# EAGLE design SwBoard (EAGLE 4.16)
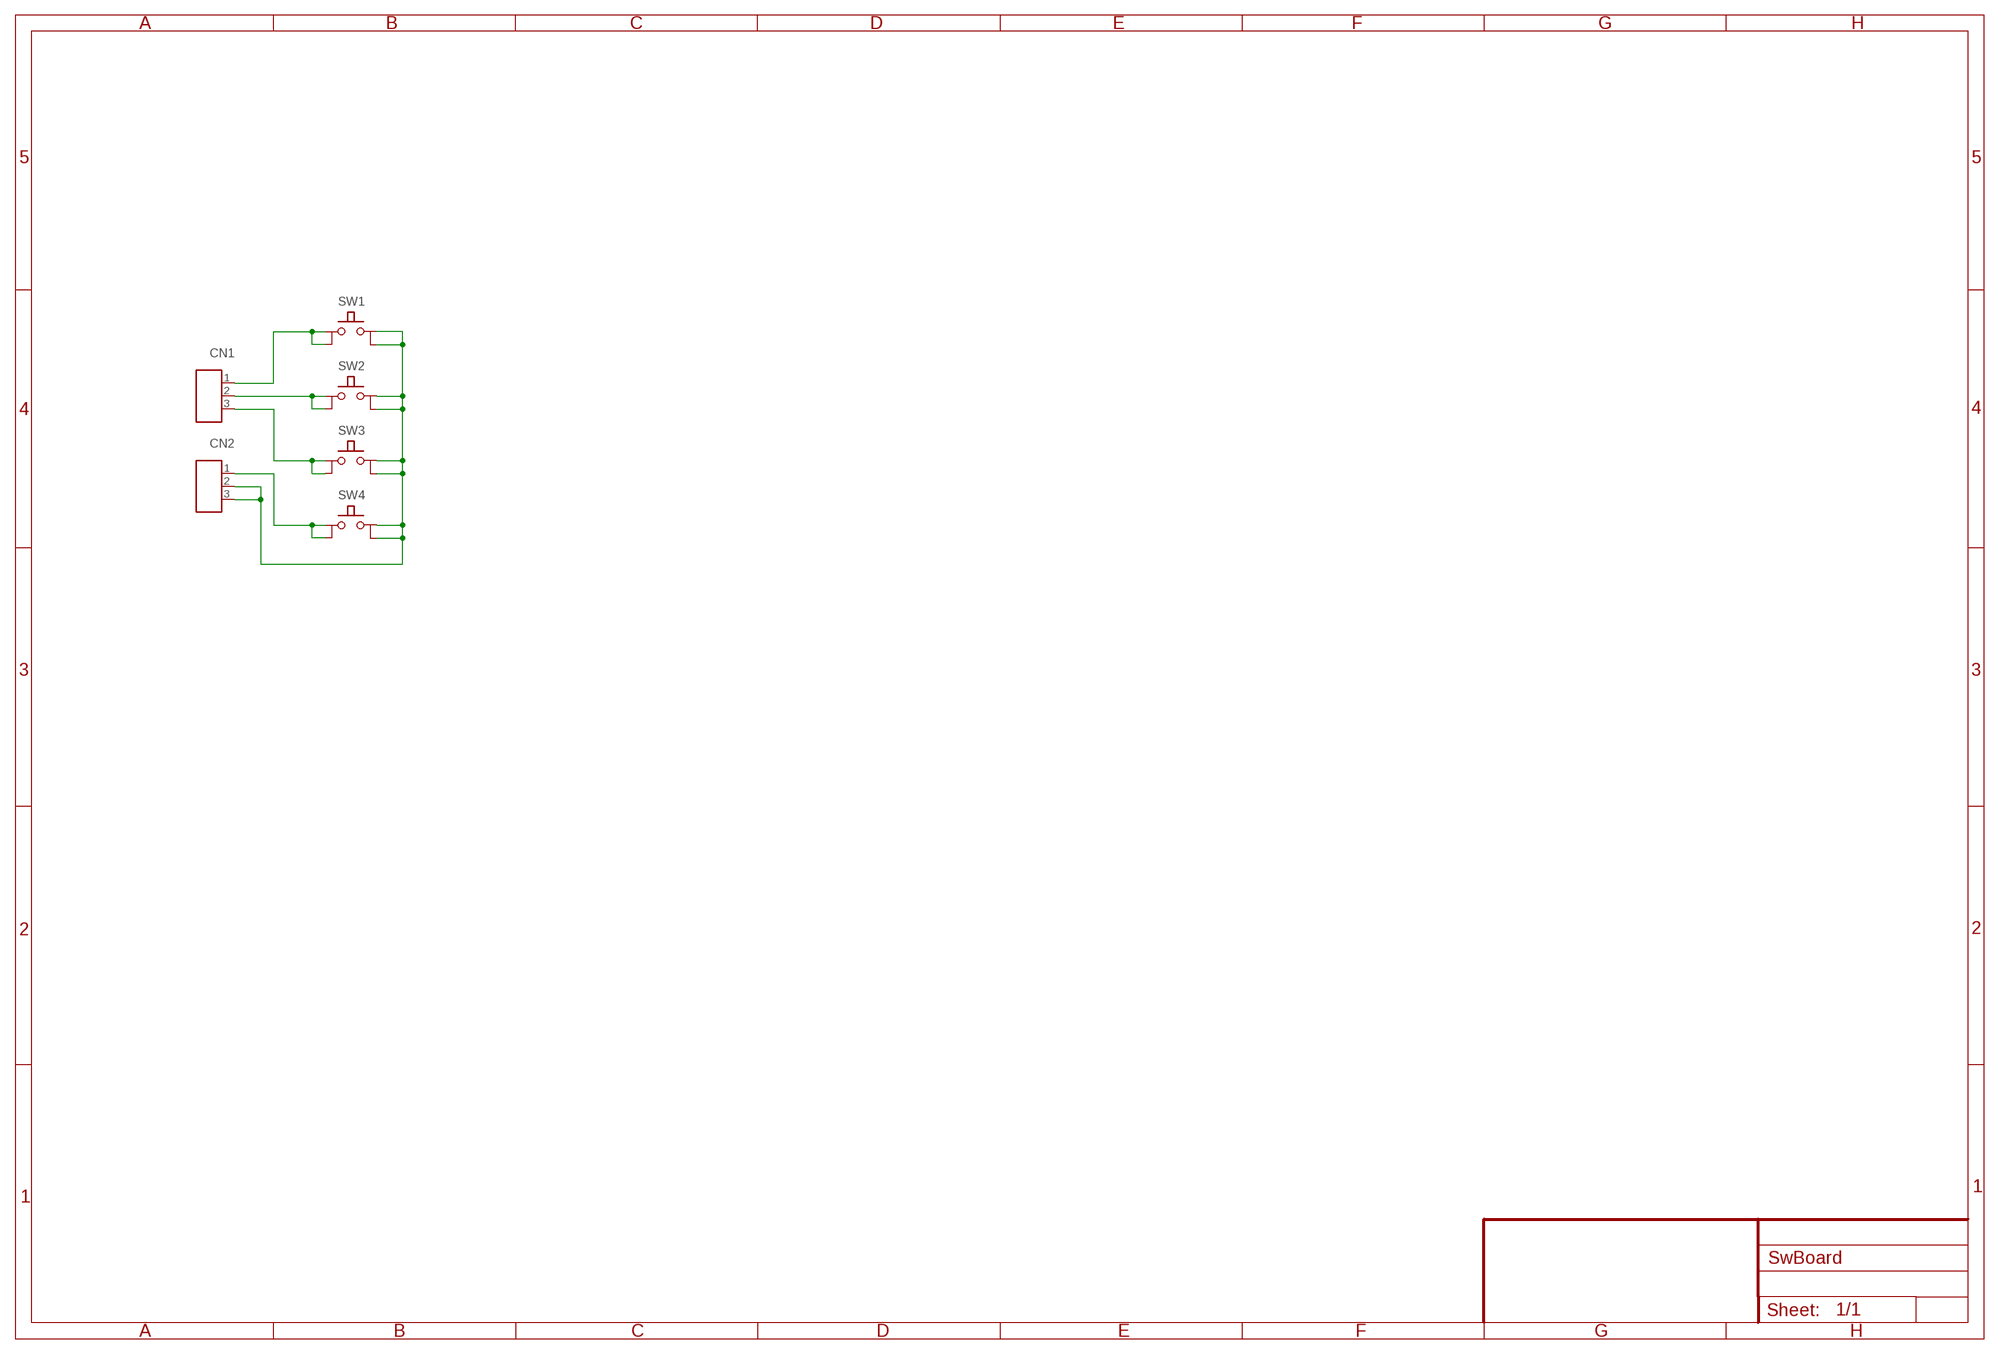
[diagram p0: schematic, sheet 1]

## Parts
CN1  CON_3PSIP3  [CON_HDR_SIP3]
CN2  CON_3PSIP3  [CON_HDR_SIP3]
SW1  PUSHSW10X10  [PUSHSW-10X10]
SW2  PUSHSW10X10  [PUSHSW-10X10]
SW3  PUSHSW10X10  [PUSHSW-10X10]
SW4  PUSHSW10X10  [PUSHSW-10X10]

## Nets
N$1: CN1.1 SW1.1 SW1.2
N$2: CN1.2 SW2.1 SW2.2
N$4: CN2.1 SW4.1 SW4.2
N$5: CN2.2 CN2.3 SW1.3 SW1.4 SW2.3 SW2.4 SW3.3 SW3.4 SW4.3 SW4.4
N$8: CN1.3 SW3.1 SW3.2

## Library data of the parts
CN1 CN2 = WirelessTemp:CON_3P
SW1-SW4 = WirelessTemp:PUSHSW

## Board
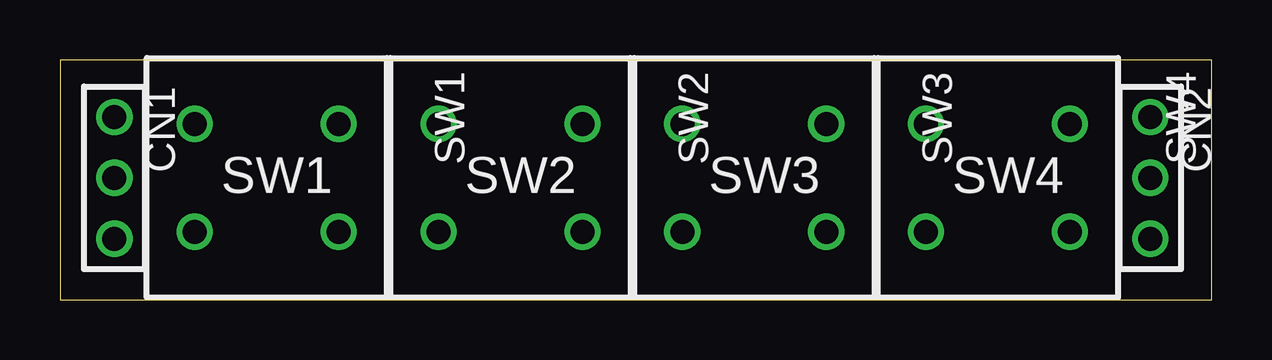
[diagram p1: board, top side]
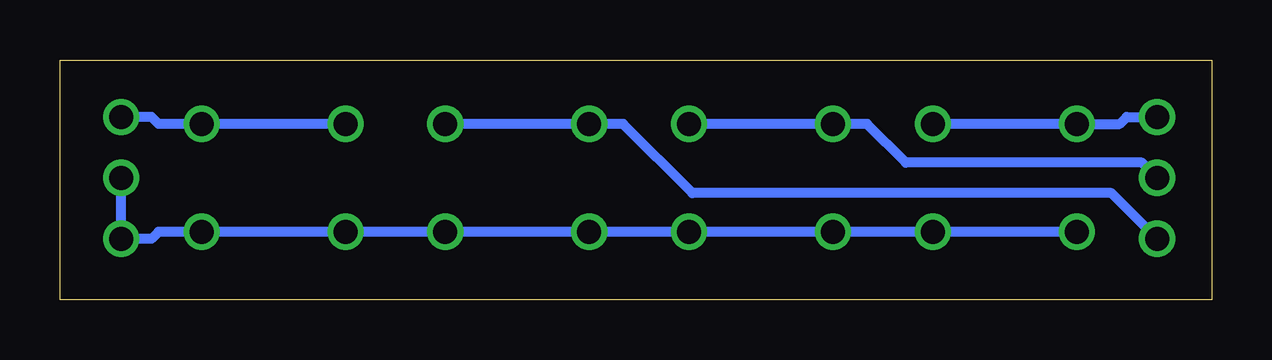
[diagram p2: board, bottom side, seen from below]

Size 48 x 10 mm. Coordinates in mm from the lower left corner, seen from the top.
Outline: 0,0 48,0 48,10 0,10 0,0
Copper layers (1*16): Top 0.035mm / dielectric 1.5mm / Bottom 0.035mm
Design rules "Olimex10mils": minimum track width 10mil, minimum drill 0.6mm, track to track 10mil, track to pad 10mil, pad to pad 10mil, via to via 10mil, smd to smd 10mil, copper to edge 40mil, drill to drill 10mil, minimum pad ring 10mil, minimum via ring 8mil, stop-mask expansion 0mil, vias tented up to drill 0mil, thermal gap 10mil

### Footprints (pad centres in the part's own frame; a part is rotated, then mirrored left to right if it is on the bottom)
CON_HDR_SIP3 = drill 1 round: 1 -2.54,0; 2 0,0; 3 2.54,0
PUSHSW-10X10 = drill 1 round: 1 -2.25,3; 2 -2.25,-3; 3 2.25,-3; 4 2.25,3

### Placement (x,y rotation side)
CN1  2.27,5.08 270 top
CN2  45.45,5.08 270 top
SW1  8.62,5.08 270 top
SW2  18.78,5.08 270 top
SW3  28.94,5.08 270 top
SW4  39.1,5.08 270 top

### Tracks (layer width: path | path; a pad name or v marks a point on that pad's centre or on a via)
N$1
  Bottom 0.406: CN1.1 3.54,7.62 3.83,7.33 SW1.2 8.62,7.33 SW1.1
N$2
  Bottom 0.406: CN1.2 2.91,5.71 12.75,5.71 14.36,7.33 SW2.2 18.78,7.33 SW2.1
N$4
  Bottom 0.406: CN2.1 44.18,7.62 43.89,7.33 SW4.1 39.42,7.33 SW4.2
N$5
  Bottom 0.406: SW1.3 SW1.4 SW2.3 SW2.4 SW3.3 SW3.4 SW4.3 SW4.4 43.89,2.83 44.18,2.54 CN2.3 CN2.2
N$8
  Bottom 0.406: CN1.3 4.17,4.45 21.64,4.45 24.52,7.33 SW3.2 28.62,7.33 SW3.1

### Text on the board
_tNames: SW1 | SW2 | SW3 | SW4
